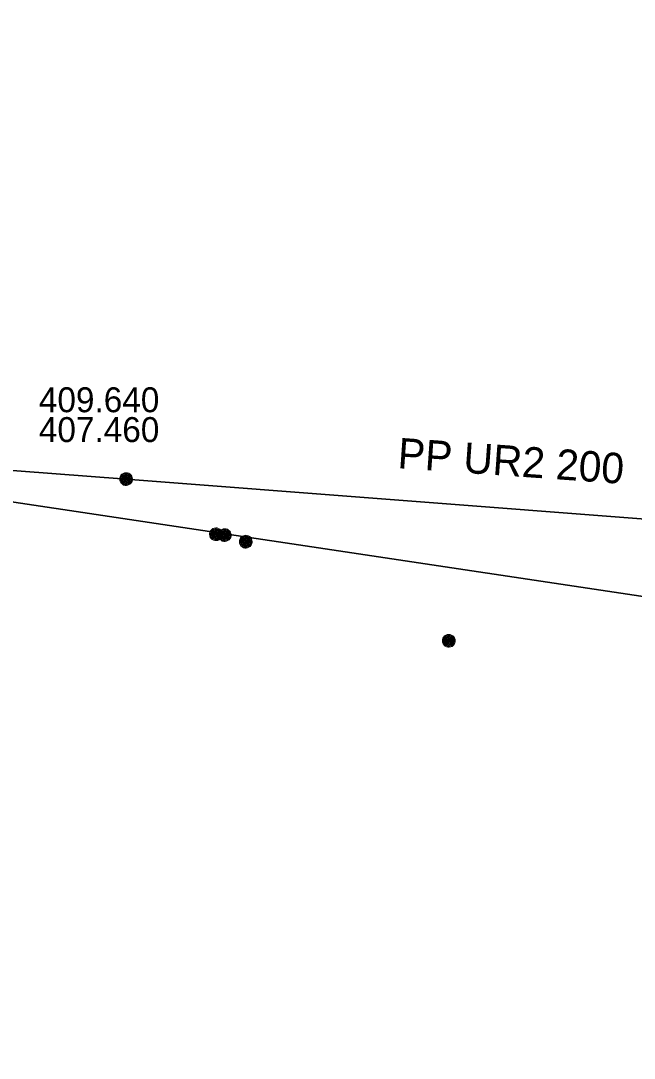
# Model space of a CAD drawing. Extents: x -867104 to -866746, y -1014489 to -1014255.
# Drawn here: x -866956.88 to -866934.73, y -1014426.06 to -1014388.58 of the extents above; entities that cross this region are included whole.
import ezdxf

# ---------------------------------------------------------------- set-up
doc = ezdxf.new("R2010")
doc.units = 0
doc.header["$LTSCALE"] = 0.44
for name, color, linetype, lineweight in [('1', 7, 'Continuous', 35), ('12', 7, 'Continuous', 13), ('21', 7, 'Continuous', 35), ('32', 7, 'Continuous', 13)]:
    doc.layers.add(name, color=color, linetype=linetype, lineweight=lineweight)

msp = doc.modelspace()

# ---------------------------------------------------------------- linework, layer by layer
at = {"layer": '1'}
msp.add_lwpolyline([(-866877.679, -1014463.149), (-866884.593, -1014451.356), (-866912.586, -1014412.658), (-867006.516, -1014398.571), (-867098.057, -1014351.101)], dxfattribs=at)
at = {"layer": '12'}
for points in [[(-866949.608, -1014407.13), (-866949.615, -1014407.078), (-866949.632, -1014407.028), (-866949.661, -1014406.984), (-866949.698, -1014406.947), (-866949.743, -1014406.92), (-866949.793, -1014406.903), (-866949.846, -1014406.899), (-866949.897, -1014406.906), (-866949.946, -1014406.925), (-866949.99, -1014406.954), (-866950.026, -1014406.993), (-866950.052, -1014407.038), (-866950.068, -1014407.089), (-866950.071, -1014407.141), (-866950.063, -1014407.193), (-866950.043, -1014407.242), (-866950.012, -1014407.285), (-866949.973, -1014407.319), (-866949.927, -1014407.345), (-866949.875, -1014407.359), (-866949.823, -1014407.361), (-866949.772, -1014407.351), (-866949.723, -1014407.33), (-866949.681, -1014407.299), (-866949.647, -1014407.258), (-866949.623, -1014407.212), (-866949.61, -1014407.161)], [(-866949.639, -1014407.13), (-866949.645, -1014407.081), (-866949.662, -1014407.035), (-866949.69, -1014406.995), (-866949.727, -1014406.963), (-866949.771, -1014406.941), (-866949.819, -1014406.93), (-866949.868, -1014406.93), (-866949.914, -1014406.943), (-866949.958, -1014406.967), (-866949.994, -1014407), (-866950.021, -1014407.041), (-866950.037, -1014407.088), (-866950.041, -1014407.137), (-866950.034, -1014407.185), (-866950.015, -1014407.23), (-866949.985, -1014407.27), (-866949.946, -1014407.301), (-866949.902, -1014407.321), (-866949.855, -1014407.331), (-866949.806, -1014407.329), (-866949.759, -1014407.314), (-866949.716, -1014407.289), (-866949.681, -1014407.255), (-866949.656, -1014407.213), (-866949.642, -1014407.166)], [(-866949.669, -1014407.13), (-866949.674, -1014407.085), (-866949.691, -1014407.043), (-866949.72, -1014407.008), (-866949.755, -1014406.981), (-866949.798, -1014406.964), (-866949.843, -1014406.959), (-866949.887, -1014406.965), (-866949.929, -1014406.984), (-866949.963, -1014407.012), (-866949.99, -1014407.049), (-866950.007, -1014407.091), (-866950.011, -1014407.136), (-866950.004, -1014407.181), (-866949.985, -1014407.222), (-866949.956, -1014407.256), (-866949.919, -1014407.282), (-866949.875, -1014407.298), (-866949.831, -1014407.301), (-866949.786, -1014407.293), (-866949.745, -1014407.273), (-866949.712, -1014407.244), (-866949.686, -1014407.206), (-866949.672, -1014407.163)], [(-866949.699, -1014407.13), (-866949.703, -1014407.089), (-866949.722, -1014407.052), (-866949.749, -1014407.021), (-866949.784, -1014407), (-866949.824, -1014406.989), (-866949.865, -1014406.991), (-866949.904, -1014407.004), (-866949.938, -1014407.028), (-866949.963, -1014407.06), (-866949.978, -1014407.098), (-866949.98, -1014407.139), (-866949.973, -1014407.179), (-866949.953, -1014407.215), (-866949.924, -1014407.244), (-866949.887, -1014407.263), (-866949.847, -1014407.271), (-866949.806, -1014407.267), (-866949.767, -1014407.252), (-866949.735, -1014407.226), (-866949.713, -1014407.192), (-866949.7, -1014407.153)], [(-866949.728, -1014407.13), (-866949.733, -1014407.094), (-866949.752, -1014407.062), (-866949.777, -1014407.037), (-866949.811, -1014407.022), (-866949.848, -1014407.019), (-866949.882, -1014407.027), (-866949.914, -1014407.047), (-866949.936, -1014407.075), (-866949.95, -1014407.109), (-866949.95, -1014407.146), (-866949.939, -1014407.181), (-866949.918, -1014407.21), (-866949.887, -1014407.231), (-866949.853, -1014407.241), (-866949.816, -1014407.239), (-866949.782, -1014407.225), (-866949.755, -1014407.202), (-866949.735, -1014407.17), (-866949.728, -1014407.135)], [(-866949.759, -1014407.13), (-866949.764, -1014407.099), (-866949.781, -1014407.073), (-866949.806, -1014407.056), (-866949.837, -1014407.049), (-866949.868, -1014407.053), (-866949.895, -1014407.07), (-866949.913, -1014407.094), (-866949.921, -1014407.125), (-866949.917, -1014407.155), (-866949.902, -1014407.183), (-866949.877, -1014407.202), (-866949.848, -1014407.211), (-866949.816, -1014407.208), (-866949.789, -1014407.194), (-866949.769, -1014407.17), (-866949.759, -1014407.141)], [(-866949.789, -1014407.13), (-866949.794, -1014407.106), (-866949.811, -1014407.088), (-866949.833, -1014407.079), (-866949.858, -1014407.082), (-866949.879, -1014407.096), (-866949.89, -1014407.118), (-866949.89, -1014407.143), (-866949.877, -1014407.164), (-866949.858, -1014407.178), (-866949.833, -1014407.181), (-866949.809, -1014407.172), (-866949.794, -1014407.154)], [(-866949.819, -1014407.13), (-866949.824, -1014407.115), (-866949.838, -1014407.109), (-866949.853, -1014407.113), (-866949.86, -1014407.127), (-866949.857, -1014407.142), (-866949.843, -1014407.151), (-866949.828, -1014407.148), (-866949.819, -1014407.136)], [(-866949.289, -1014407.16), (-866949.295, -1014407.108), (-866949.312, -1014407.058), (-866949.341, -1014407.014), (-866949.378, -1014406.977), (-866949.423, -1014406.95), (-866949.473, -1014406.933), (-866949.526, -1014406.929), (-866949.578, -1014406.936), (-866949.627, -1014406.955), (-866949.67, -1014406.984), (-866949.706, -1014407.023), (-866949.732, -1014407.068), (-866949.748, -1014407.119), (-866949.751, -1014407.171), (-866949.743, -1014407.223), (-866949.723, -1014407.272), (-866949.692, -1014407.315), (-866949.653, -1014407.349), (-866949.607, -1014407.375), (-866949.556, -1014407.389), (-866949.503, -1014407.391), (-866949.452, -1014407.381), (-866949.404, -1014407.36), (-866949.361, -1014407.329), (-866949.327, -1014407.288), (-866949.303, -1014407.242), (-866949.291, -1014407.191)], [(-866949.319, -1014407.16), (-866949.325, -1014407.111), (-866949.342, -1014407.065), (-866949.37, -1014407.025), (-866949.407, -1014406.993), (-866949.451, -1014406.971), (-866949.499, -1014406.96), (-866949.548, -1014406.96), (-866949.595, -1014406.973), (-866949.638, -1014406.997), (-866949.674, -1014407.03), (-866949.701, -1014407.071), (-866949.717, -1014407.118), (-866949.721, -1014407.167), (-866949.714, -1014407.215), (-866949.695, -1014407.26), (-866949.665, -1014407.3), (-866949.627, -1014407.331), (-866949.583, -1014407.351), (-866949.535, -1014407.361), (-866949.486, -1014407.359), (-866949.439, -1014407.344), (-866949.396, -1014407.319), (-866949.362, -1014407.285), (-866949.336, -1014407.243), (-866949.322, -1014407.196)], [(-866949.349, -1014407.16), (-866949.355, -1014407.115), (-866949.372, -1014407.073), (-866949.4, -1014407.038), (-866949.436, -1014407.011), (-866949.478, -1014406.994), (-866949.523, -1014406.989), (-866949.568, -1014406.995), (-866949.609, -1014407.014), (-866949.644, -1014407.042), (-866949.671, -1014407.079), (-866949.687, -1014407.121), (-866949.691, -1014407.166), (-866949.684, -1014407.211), (-866949.665, -1014407.252), (-866949.636, -1014407.286), (-866949.599, -1014407.312), (-866949.556, -1014407.328), (-866949.511, -1014407.331), (-866949.466, -1014407.323), (-866949.426, -1014407.303), (-866949.392, -1014407.274), (-866949.366, -1014407.236), (-866949.352, -1014407.193)], [(-866949.379, -1014407.16), (-866949.384, -1014407.119), (-866949.402, -1014407.082), (-866949.429, -1014407.051), (-866949.464, -1014407.03), (-866949.504, -1014407.019), (-866949.545, -1014407.021), (-866949.584, -1014407.034), (-866949.618, -1014407.058), (-866949.643, -1014407.09), (-866949.658, -1014407.128), (-866949.661, -1014407.169), (-866949.653, -1014407.209), (-866949.633, -1014407.245), (-866949.604, -1014407.274), (-866949.567, -1014407.293), (-866949.527, -1014407.301), (-866949.486, -1014407.297), (-866949.448, -1014407.282), (-866949.416, -1014407.256), (-866949.393, -1014407.222), (-866949.38, -1014407.183)], [(-866949.409, -1014407.16), (-866949.414, -1014407.124), (-866949.432, -1014407.092), (-866949.458, -1014407.067), (-866949.492, -1014407.052), (-866949.528, -1014407.049), (-866949.563, -1014407.057), (-866949.594, -1014407.077), (-866949.617, -1014407.105), (-866949.63, -1014407.139), (-866949.63, -1014407.176), (-866949.619, -1014407.211), (-866949.598, -1014407.24), (-866949.568, -1014407.261), (-866949.533, -1014407.271), (-866949.496, -1014407.269), (-866949.462, -1014407.255), (-866949.435, -1014407.232), (-866949.416, -1014407.2), (-866949.409, -1014407.165)], [(-866949.439, -1014407.16), (-866949.444, -1014407.129), (-866949.461, -1014407.103), (-866949.487, -1014407.086), (-866949.517, -1014407.079), (-866949.548, -1014407.083), (-866949.575, -1014407.1), (-866949.593, -1014407.124), (-866949.601, -1014407.155), (-866949.597, -1014407.185), (-866949.582, -1014407.213), (-866949.558, -1014407.232), (-866949.528, -1014407.241), (-866949.497, -1014407.238), (-866949.469, -1014407.224), (-866949.449, -1014407.2), (-866949.439, -1014407.171)], [(-866949.469, -1014407.16), (-866949.474, -1014407.136), (-866949.491, -1014407.118), (-866949.514, -1014407.109), (-866949.538, -1014407.112), (-866949.559, -1014407.126), (-866949.57, -1014407.148), (-866949.57, -1014407.173), (-866949.558, -1014407.194), (-866949.538, -1014407.208), (-866949.513, -1014407.211), (-866949.49, -1014407.202), (-866949.474, -1014407.184)], [(-866949.499, -1014407.16), (-866949.504, -1014407.145), (-866949.519, -1014407.139), (-866949.534, -1014407.143), (-866949.541, -1014407.157), (-866949.537, -1014407.172), (-866949.524, -1014407.181), (-866949.509, -1014407.178), (-866949.499, -1014407.166)], [(-866948.529, -1014407.4), (-866948.535, -1014407.348), (-866948.552, -1014407.298), (-866948.581, -1014407.254), (-866948.618, -1014407.217), (-866948.663, -1014407.19), (-866948.713, -1014407.173), (-866948.766, -1014407.169), (-866948.818, -1014407.176), (-866948.867, -1014407.195), (-866948.91, -1014407.224), (-866948.946, -1014407.263), (-866948.972, -1014407.308), (-866948.988, -1014407.359), (-866948.991, -1014407.411), (-866948.983, -1014407.463), (-866948.963, -1014407.512), (-866948.932, -1014407.555), (-866948.893, -1014407.589), (-866948.847, -1014407.615), (-866948.796, -1014407.629), (-866948.743, -1014407.631), (-866948.692, -1014407.621), (-866948.644, -1014407.6), (-866948.601, -1014407.569), (-866948.567, -1014407.528), (-866948.543, -1014407.482), (-866948.531, -1014407.431)], [(-866948.559, -1014407.4), (-866948.565, -1014407.351), (-866948.582, -1014407.305), (-866948.61, -1014407.265), (-866948.647, -1014407.233), (-866948.691, -1014407.211), (-866948.739, -1014407.2), (-866948.788, -1014407.2), (-866948.835, -1014407.213), (-866948.878, -1014407.237), (-866948.914, -1014407.27), (-866948.941, -1014407.311), (-866948.957, -1014407.358), (-866948.961, -1014407.407), (-866948.954, -1014407.455), (-866948.935, -1014407.5), (-866948.905, -1014407.54), (-866948.867, -1014407.571), (-866948.823, -1014407.591), (-866948.775, -1014407.601), (-866948.726, -1014407.599), (-866948.679, -1014407.584), (-866948.636, -1014407.559), (-866948.602, -1014407.525), (-866948.576, -1014407.483), (-866948.562, -1014407.436)], [(-866948.589, -1014407.4), (-866948.595, -1014407.355), (-866948.612, -1014407.313), (-866948.64, -1014407.278), (-866948.676, -1014407.251), (-866948.718, -1014407.234), (-866948.763, -1014407.229), (-866948.808, -1014407.235), (-866948.849, -1014407.254), (-866948.884, -1014407.282), (-866948.911, -1014407.319), (-866948.927, -1014407.361), (-866948.931, -1014407.406), (-866948.924, -1014407.451), (-866948.905, -1014407.492), (-866948.876, -1014407.526), (-866948.839, -1014407.552), (-866948.796, -1014407.568), (-866948.751, -1014407.571), (-866948.706, -1014407.563), (-866948.666, -1014407.543), (-866948.632, -1014407.514), (-866948.606, -1014407.476), (-866948.592, -1014407.433)], [(-866948.619, -1014407.4), (-866948.624, -1014407.359), (-866948.642, -1014407.322), (-866948.669, -1014407.291), (-866948.704, -1014407.27), (-866948.744, -1014407.259), (-866948.785, -1014407.261), (-866948.824, -1014407.274), (-866948.858, -1014407.298), (-866948.883, -1014407.33), (-866948.898, -1014407.368), (-866948.901, -1014407.409), (-866948.893, -1014407.449), (-866948.873, -1014407.485), (-866948.844, -1014407.514), (-866948.807, -1014407.533), (-866948.767, -1014407.541), (-866948.726, -1014407.537), (-866948.688, -1014407.522), (-866948.656, -1014407.496), (-866948.633, -1014407.462), (-866948.62, -1014407.423)], [(-866948.649, -1014407.4), (-866948.654, -1014407.364), (-866948.672, -1014407.332), (-866948.698, -1014407.307), (-866948.732, -1014407.292), (-866948.768, -1014407.289), (-866948.803, -1014407.297), (-866948.834, -1014407.317), (-866948.857, -1014407.345), (-866948.87, -1014407.379), (-866948.87, -1014407.416), (-866948.859, -1014407.451), (-866948.838, -1014407.48), (-866948.808, -1014407.501), (-866948.773, -1014407.511), (-866948.736, -1014407.509), (-866948.702, -1014407.495), (-866948.675, -1014407.472), (-866948.656, -1014407.44), (-866948.649, -1014407.405)], [(-866948.679, -1014407.4), (-866948.684, -1014407.369), (-866948.701, -1014407.343), (-866948.727, -1014407.326), (-866948.757, -1014407.319), (-866948.788, -1014407.323), (-866948.815, -1014407.34), (-866948.833, -1014407.364), (-866948.841, -1014407.395), (-866948.837, -1014407.425), (-866948.822, -1014407.453), (-866948.798, -1014407.472), (-866948.768, -1014407.481), (-866948.737, -1014407.478), (-866948.709, -1014407.464), (-866948.689, -1014407.44), (-866948.679, -1014407.411)], [(-866948.709, -1014407.4), (-866948.714, -1014407.376), (-866948.731, -1014407.358), (-866948.754, -1014407.349), (-866948.778, -1014407.352), (-866948.799, -1014407.366), (-866948.81, -1014407.388), (-866948.81, -1014407.413), (-866948.798, -1014407.434), (-866948.778, -1014407.448), (-866948.753, -1014407.451), (-866948.73, -1014407.442), (-866948.714, -1014407.424)], [(-866948.739, -1014407.4), (-866948.744, -1014407.385), (-866948.759, -1014407.379), (-866948.774, -1014407.383), (-866948.781, -1014407.397), (-866948.777, -1014407.412), (-866948.764, -1014407.421), (-866948.749, -1014407.418), (-866948.739, -1014407.406)]]:
    msp.add_lwpolyline(points, close=True, dxfattribs=at)
at = {"layer": '21'}
msp.add_line((-866922.726, -1014407.49), (-866953.081, -1014405.138), dxfattribs=at)
msp.add_lwpolyline([(-866953.081, -1014405.138), (-866972.671, -1014403.647), (-866981.237, -1014402.954), (-866985.536, -1014402.661), (-867007.098, -1014400.979), (-867018.151, -1014403.08)], dxfattribs=at)
at = {"layer": '32'}
for points in [[(-866952.85, -1014405.138), (-866952.856, -1014405.086), (-866952.873, -1014405.036), (-866952.902, -1014404.992), (-866952.939, -1014404.955), (-866952.984, -1014404.928), (-866953.034, -1014404.911), (-866953.087, -1014404.907), (-866953.139, -1014404.914), (-866953.188, -1014404.933), (-866953.231, -1014404.962), (-866953.267, -1014405.001), (-866953.293, -1014405.046), (-866953.309, -1014405.097), (-866953.312, -1014405.149), (-866953.304, -1014405.201), (-866953.284, -1014405.25), (-866953.253, -1014405.293), (-866953.214, -1014405.327), (-866953.168, -1014405.353), (-866953.117, -1014405.367), (-866953.064, -1014405.369), (-866953.013, -1014405.359), (-866952.965, -1014405.338), (-866952.922, -1014405.307), (-866952.888, -1014405.266), (-866952.864, -1014405.22), (-866952.852, -1014405.169)], [(-866952.88, -1014405.138), (-866952.886, -1014405.089), (-866952.903, -1014405.043), (-866952.931, -1014405.003), (-866952.968, -1014404.971), (-866953.012, -1014404.949), (-866953.06, -1014404.938), (-866953.109, -1014404.938), (-866953.156, -1014404.951), (-866953.199, -1014404.975), (-866953.235, -1014405.008), (-866953.262, -1014405.049), (-866953.278, -1014405.096), (-866953.282, -1014405.145), (-866953.275, -1014405.193), (-866953.256, -1014405.238), (-866953.226, -1014405.278), (-866953.188, -1014405.309), (-866953.144, -1014405.329), (-866953.096, -1014405.339), (-866953.047, -1014405.337), (-866953, -1014405.322), (-866952.957, -1014405.297), (-866952.923, -1014405.263), (-866952.897, -1014405.221), (-866952.883, -1014405.174)], [(-866952.91, -1014405.138), (-866952.916, -1014405.093), (-866952.933, -1014405.051), (-866952.961, -1014405.016), (-866952.997, -1014404.989), (-866953.039, -1014404.972), (-866953.084, -1014404.967), (-866953.129, -1014404.973), (-866953.17, -1014404.992), (-866953.205, -1014405.02), (-866953.232, -1014405.057), (-866953.248, -1014405.099), (-866953.252, -1014405.144), (-866953.245, -1014405.189), (-866953.226, -1014405.23), (-866953.197, -1014405.264), (-866953.16, -1014405.29), (-866953.117, -1014405.306), (-866953.072, -1014405.309), (-866953.027, -1014405.301), (-866952.987, -1014405.281), (-866952.953, -1014405.252), (-866952.927, -1014405.214), (-866952.913, -1014405.171)], [(-866952.94, -1014405.138), (-866952.945, -1014405.097), (-866952.963, -1014405.06), (-866952.99, -1014405.029), (-866953.025, -1014405.008), (-866953.065, -1014404.997), (-866953.106, -1014404.999), (-866953.145, -1014405.012), (-866953.179, -1014405.036), (-866953.204, -1014405.068), (-866953.219, -1014405.106), (-866953.222, -1014405.147), (-866953.214, -1014405.187), (-866953.194, -1014405.223), (-866953.165, -1014405.252), (-866953.128, -1014405.271), (-866953.088, -1014405.279), (-866953.047, -1014405.275), (-866953.009, -1014405.26), (-866952.977, -1014405.234), (-866952.954, -1014405.2), (-866952.941, -1014405.161)], [(-866952.97, -1014405.138), (-866952.975, -1014405.102), (-866952.993, -1014405.07), (-866953.019, -1014405.045), (-866953.053, -1014405.03), (-866953.089, -1014405.027), (-866953.124, -1014405.035), (-866953.155, -1014405.055), (-866953.178, -1014405.083), (-866953.191, -1014405.117), (-866953.191, -1014405.154), (-866953.18, -1014405.189), (-866953.159, -1014405.218), (-866953.129, -1014405.239), (-866953.094, -1014405.249), (-866953.057, -1014405.247), (-866953.023, -1014405.233), (-866952.996, -1014405.21), (-866952.977, -1014405.178), (-866952.97, -1014405.143)], [(-866953, -1014405.138), (-866953.005, -1014405.107), (-866953.022, -1014405.081), (-866953.048, -1014405.064), (-866953.078, -1014405.057), (-866953.109, -1014405.061), (-866953.136, -1014405.078), (-866953.154, -1014405.102), (-866953.162, -1014405.133), (-866953.158, -1014405.163), (-866953.143, -1014405.191), (-866953.119, -1014405.21), (-866953.089, -1014405.219), (-866953.058, -1014405.216), (-866953.03, -1014405.202), (-866953.01, -1014405.178), (-866953, -1014405.149)], [(-866953.03, -1014405.138), (-866953.035, -1014405.114), (-866953.052, -1014405.096), (-866953.075, -1014405.087), (-866953.099, -1014405.09), (-866953.12, -1014405.104), (-866953.131, -1014405.126), (-866953.131, -1014405.151), (-866953.119, -1014405.172), (-866953.099, -1014405.186), (-866953.074, -1014405.189), (-866953.051, -1014405.18), (-866953.035, -1014405.162)], [(-866953.06, -1014405.138), (-866953.065, -1014405.123), (-866953.08, -1014405.117), (-866953.095, -1014405.121), (-866953.102, -1014405.135), (-866953.098, -1014405.15), (-866953.085, -1014405.159), (-866953.07, -1014405.156), (-866953.06, -1014405.144)], [(-866941.199, -1014410.98), (-866941.205, -1014410.928), (-866941.222, -1014410.878), (-866941.251, -1014410.834), (-866941.288, -1014410.797), (-866941.333, -1014410.77), (-866941.383, -1014410.753), (-866941.436, -1014410.749), (-866941.488, -1014410.756), (-866941.537, -1014410.775), (-866941.58, -1014410.804), (-866941.616, -1014410.843), (-866941.642, -1014410.888), (-866941.658, -1014410.939), (-866941.661, -1014410.991), (-866941.653, -1014411.043), (-866941.633, -1014411.092), (-866941.602, -1014411.135), (-866941.563, -1014411.169), (-866941.517, -1014411.195), (-866941.466, -1014411.209), (-866941.413, -1014411.211), (-866941.362, -1014411.201), (-866941.314, -1014411.18), (-866941.271, -1014411.149), (-866941.237, -1014411.108), (-866941.213, -1014411.062), (-866941.201, -1014411.011)], [(-866941.229, -1014410.98), (-866941.235, -1014410.931), (-866941.252, -1014410.885), (-866941.28, -1014410.845), (-866941.317, -1014410.813), (-866941.361, -1014410.791), (-866941.409, -1014410.78), (-866941.458, -1014410.78), (-866941.505, -1014410.793), (-866941.548, -1014410.817), (-866941.584, -1014410.85), (-866941.611, -1014410.891), (-866941.627, -1014410.938), (-866941.631, -1014410.987), (-866941.624, -1014411.035), (-866941.605, -1014411.08), (-866941.575, -1014411.12), (-866941.537, -1014411.151), (-866941.493, -1014411.171), (-866941.445, -1014411.181), (-866941.396, -1014411.179), (-866941.349, -1014411.164), (-866941.306, -1014411.139), (-866941.272, -1014411.105), (-866941.246, -1014411.063), (-866941.232, -1014411.016)], [(-866941.259, -1014410.98), (-866941.265, -1014410.935), (-866941.282, -1014410.893), (-866941.31, -1014410.858), (-866941.346, -1014410.831), (-866941.388, -1014410.814), (-866941.433, -1014410.809), (-866941.478, -1014410.815), (-866941.519, -1014410.834), (-866941.554, -1014410.862), (-866941.581, -1014410.899), (-866941.597, -1014410.941), (-866941.601, -1014410.986), (-866941.594, -1014411.031), (-866941.575, -1014411.072), (-866941.546, -1014411.106), (-866941.509, -1014411.132), (-866941.466, -1014411.148), (-866941.421, -1014411.151), (-866941.376, -1014411.143), (-866941.336, -1014411.123), (-866941.302, -1014411.094), (-866941.276, -1014411.056), (-866941.262, -1014411.013)], [(-866941.289, -1014410.98), (-866941.294, -1014410.939), (-866941.312, -1014410.902), (-866941.339, -1014410.871), (-866941.374, -1014410.85), (-866941.414, -1014410.839), (-866941.455, -1014410.841), (-866941.494, -1014410.854), (-866941.528, -1014410.878), (-866941.553, -1014410.91), (-866941.568, -1014410.948), (-866941.571, -1014410.989), (-866941.563, -1014411.029), (-866941.543, -1014411.065), (-866941.514, -1014411.094), (-866941.477, -1014411.113), (-866941.437, -1014411.121), (-866941.396, -1014411.117), (-866941.358, -1014411.102), (-866941.326, -1014411.076), (-866941.303, -1014411.042), (-866941.29, -1014411.003)], [(-866941.319, -1014410.98), (-866941.324, -1014410.944), (-866941.342, -1014410.912), (-866941.368, -1014410.887), (-866941.402, -1014410.872), (-866941.438, -1014410.869), (-866941.473, -1014410.877), (-866941.504, -1014410.897), (-866941.527, -1014410.925), (-866941.54, -1014410.959), (-866941.54, -1014410.996), (-866941.529, -1014411.031), (-866941.508, -1014411.06), (-866941.478, -1014411.081), (-866941.443, -1014411.091), (-866941.406, -1014411.089), (-866941.372, -1014411.075), (-866941.345, -1014411.052), (-866941.326, -1014411.02), (-866941.319, -1014410.985)], [(-866941.349, -1014410.98), (-866941.354, -1014410.949), (-866941.371, -1014410.923), (-866941.397, -1014410.906), (-866941.427, -1014410.899), (-866941.458, -1014410.903), (-866941.485, -1014410.92), (-866941.503, -1014410.944), (-866941.511, -1014410.975), (-866941.507, -1014411.005), (-866941.492, -1014411.033), (-866941.468, -1014411.052), (-866941.438, -1014411.061), (-866941.407, -1014411.058), (-866941.379, -1014411.044), (-866941.359, -1014411.02), (-866941.349, -1014410.991)], [(-866941.379, -1014410.98), (-866941.384, -1014410.956), (-866941.401, -1014410.938), (-866941.424, -1014410.929), (-866941.448, -1014410.932), (-866941.469, -1014410.946), (-866941.48, -1014410.968), (-866941.48, -1014410.993), (-866941.468, -1014411.014), (-866941.448, -1014411.028), (-866941.423, -1014411.031), (-866941.4, -1014411.022), (-866941.384, -1014411.004)], [(-866941.409, -1014410.98), (-866941.414, -1014410.965), (-866941.429, -1014410.959), (-866941.444, -1014410.963), (-866941.451, -1014410.977), (-866941.447, -1014410.992), (-866941.434, -1014411.001), (-866941.419, -1014410.998), (-866941.409, -1014410.986)]]:
    msp.add_lwpolyline(points, close=True, dxfattribs=at)

# ---------------------------------------------------------------- texts
at = {"layer": '1'}
for s, p in [('409.640 ', (-866956.23, -1014402.722)), ('407.460 ', (-866956.23, -1014403.799))]:
    msp.add_text(s, height=0.9, dxfattribs=at).set_placement(p)
msp.add_text('PP UR2 200', height=1.1, rotation=356, dxfattribs=at).set_placement((-866943.298, -1014404.742))

doc.saveas('drawing.dxf')
